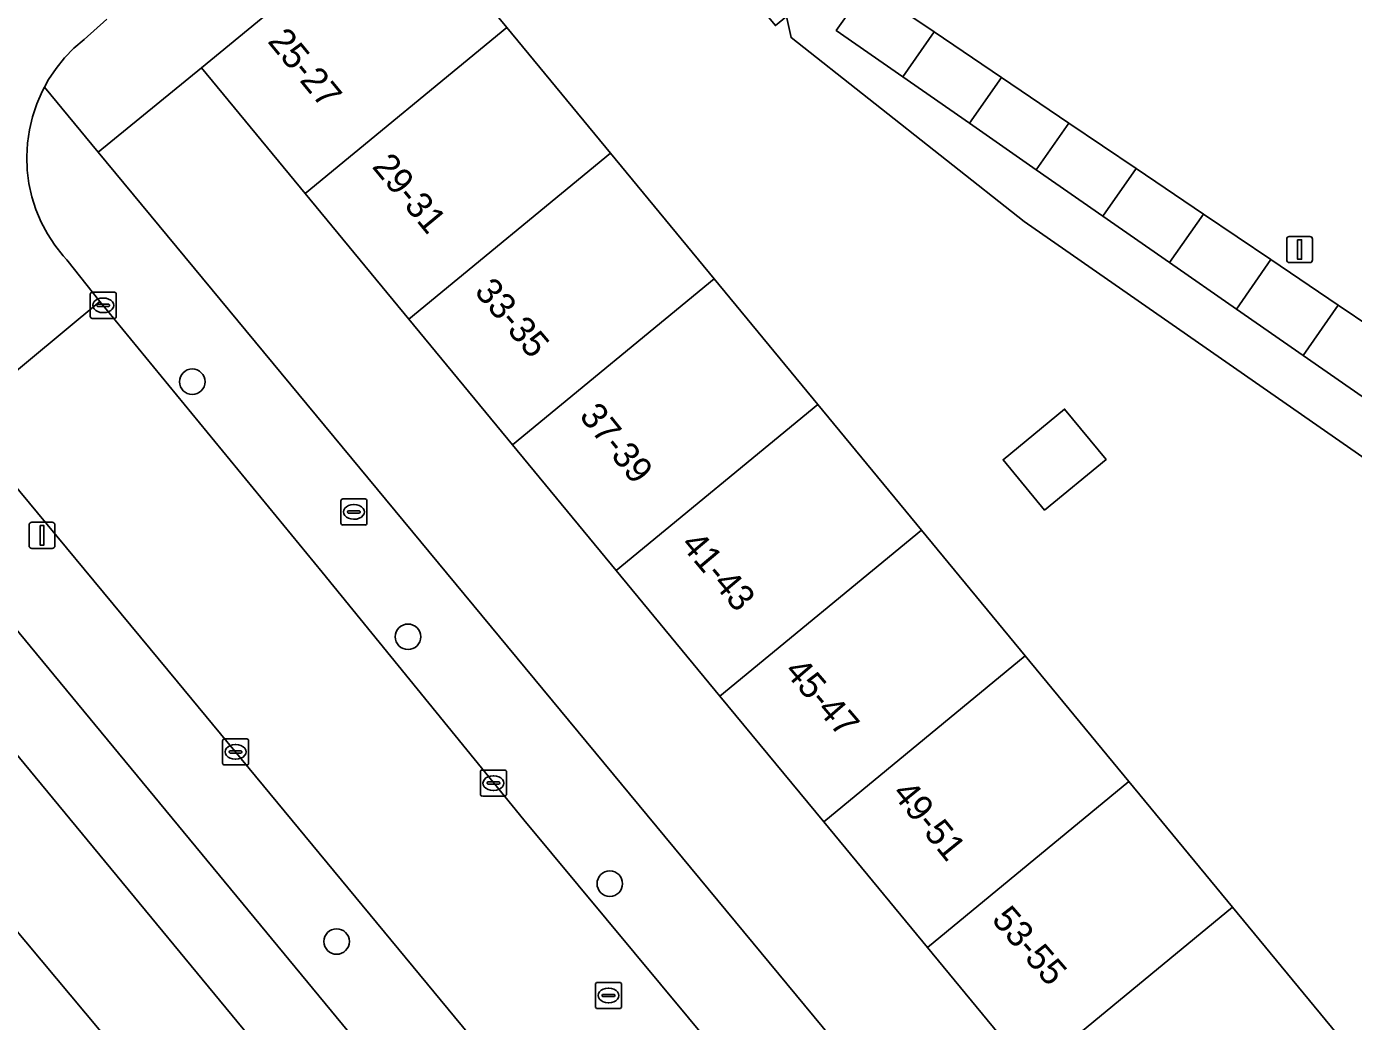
# Model space of a CAD drawing. Extents: x 159279 to 160377, y 384531 to 385888.
# Drawn here: x 159508.6 to 159559.4, y 385070.4 to 385108.5 of the extents above; entities that cross this region are included whole.
import ezdxf

# ---------------------------------------------------------------- set-up
doc = ezdxf.new("R2010")
doc.units = 0
for name, color, linetype in [('IMGEO_Berm_groen', 7, 'Continuous'), ('IMGEO_Boom', 7, 'Continuous'), ('IMGEO_Brandkraan', 7, 'Continuous'), ('IMGEO_Erf', 7, 'Continuous'), ('IMGEO_Fietspad_open', 7, 'Continuous'), ('IMGEO_Kolk', 7, 'Continuous'), ('IMGEO_Lichtmast', 7, 'Continuous'), ('IMGEO_Pand', 7, 'Continuous'), ('IMGEO_Pand_nummerreeks', 7, 'Continuous'), ('IMGEO_Rijbaan_lokaal_open', 7, 'Continuous'), ('IMGEO_Rioolput', 7, 'Continuous'), ('IMGEO_Voetpad_halfverhard', 7, 'Continuous'), ('IMGEO_Voetpad_open', 7, 'Continuous')]:
    doc.layers.add(name, color=color, linetype=linetype)

msp = doc.modelspace()

# ---------------------------------------------------------------- linework, layer by layer
at = {"layer": 'IMGEO_Berm_groen'}
msp.add_lwpolyline([(159548.464, 385042.144), (159514.365, 385083.398), (159506.522, 385092.845), (159505.985, 385093.489), (159501.236, 385099.246), (159500, 385098.236), (159498.552, 385097.053), (159500, 385095.299), (159503.322, 385091.276), (159555.379, 385028.229), (159578.758, 385000), (159595.338, 384979.98), (159599.426, 384980.154), (159597.476, 384982.555), (159597.475, 384982.557), (159592.173, 384989.226), (159583.28, 385000), (159567.948, 385018.574), (159561.44, 385026.479)], dxfattribs=at)
msp.add_lwpolyline([(159500.989, 385089.338), (159500, 385090.536), (159496.167, 385095.18), (159492.847, 385092.45), (159504.614, 385078.11), (159526.057, 385052.483), (159550.045, 385023.323), (159581.191, 384985.668), (159588.005, 384977.223), (159607.336, 384953.936), (159608.885, 384958.557), (159603.858, 384964.651), (159595.683, 384974.49), (159595.245, 384975.018), (159581.364, 384991.732), (159572.259, 385003.065), (159553.043, 385026.266)], close=True, dxfattribs=at)
at = {"layer": 'IMGEO_Boom'}
for centre in [(159514.928, 385094.896), (159523.196, 385085.12), (159530.928, 385075.656), (159520.459, 385073.439)]:
    msp.add_circle(centre, 0.489, dxfattribs=at)
at = {"layer": 'IMGEO_Brandkraan'}
for p, q in [((159520.621, 385089.478), (159520.621, 385090.33)), ((159520.696, 385090.404), (159521.548, 385090.404)), ((159521.622, 385090.33), (159521.622, 385089.478)), ((159520.88, 385089.898), (159520.88, 385089.91)), ((159521.318, 385089.861), (159520.92, 385089.861)), ((159520.923, 385089.947), (159521.321, 385089.947)), ((159521.109, 385090.184), (159521.134, 385090.184)), ((159521.364, 385089.91), (159521.364, 385089.898)), ((159521.548, 385089.404), (159520.696, 385089.404)), ((159521.132, 385089.624), (159521.107, 385089.624))]:
    msp.add_line(p, q, dxfattribs=at)
for points in [[(159520.621, 385089.478), (159520.621, 385090.33)], [(159520.696, 385090.404), (159521.548, 385090.404)], [(159521.622, 385090.33), (159521.622, 385089.478)], [(159521.548, 385089.404), (159520.696, 385089.404)]]:
    msp.add_lwpolyline(points, dxfattribs=at)
for centre, radius, start, end in [((159520.698, 385090.328), 0.0765, 91.552, 178.448), ((159520.698, 385090.328), 0.0765, 91.552, 178.448), ((159521.546, 385090.328), 0.0765, 1.552, 88.448), ((159521.546, 385090.328), 0.0765, 1.552, 88.448), ((159520.92, 385089.907), 0.0403, 85.8775, 175.7526), ((159520.917, 385089.897), 0.0366, 178.938, 274.7102), ((159521.321, 385089.904), 0.043, 264.8664, 352.4533), ((159521.325, 385089.909), 0.0386, 1.7309, 96.639), ((159520.698, 385089.48), 0.0765, 181.552, 268.448), ((159520.698, 385089.48), 0.0765, 181.552, 268.448), ((159521.546, 385089.48), 0.0765, 271.552, 358.448), ((159521.546, 385089.48), 0.0765, 271.552, 358.448)]:
    msp.add_arc(centre, radius, start, end, dxfattribs=at)
for centre, major_axis, ratio, start_param, end_param in [((159521.108, 385089.904), (-0.387, 0.002), 0.722429, 4.712389, 7.853982), ((159521.133, 385089.904), (-0.39, 0.002), 0.717154, 1.570796, 4.712389)]:
    msp.add_ellipse(centre, major_axis=major_axis, ratio=ratio, start_param=start_param, end_param=end_param, dxfattribs=at)
at = {"layer": 'IMGEO_Erf'}
msp.add_lwpolyline([(159560.206, 385120.511), (159555.815, 385123.374), (159553.961, 385124.582), (159548.542, 385120.063), (159546.841, 385118.672), (159546.787, 385118.736), (159543.539, 385115.984), (159540.221, 385119.961), (159536.5, 385124.478), (159534.056, 385122.447), (159532.547, 385121.206), (159532.576, 385121.17), (159541.494, 385110.217), (159541.312, 385109.686), (159543.361, 385108.3), (159545.941, 385106.555), (159548.52, 385104.81), (159551.1, 385103.065), (159553.68, 385101.321), (159556.259, 385099.576), (159558.839, 385097.831), (159561.419, 385096.086)], dxfattribs=at)
for points in [[(159546.804, 385101.034), (159537.877, 385108.087), (159537.695, 385108.891), (159537.274, 385108.543), (159533.299, 385113.344), (159535.261, 385114.967), (159533.216, 385117.531), (159531.308, 385116.022), (159529.284, 385118.582), (159523.004, 385113.291), (159526.979, 385108.475), (159530.953, 385103.659), (159534.926, 385098.843), (159538.9, 385094.026), (159542.874, 385089.21), (159546.848, 385084.394), (159550.822, 385079.578), (159554.796, 385074.761), (159558.769, 385069.945), (159562.743, 385065.129), (159566.717, 385060.312), (159570.691, 385055.496), (159580.752, 385063.798), (159587.133, 385072.965)], [(159543.1, 385073.206), (159539.126, 385078.022), (159535.152, 385082.839), (159531.178, 385087.655), (159527.204, 385092.471), (159523.231, 385097.288), (159519.257, 385102.104), (159515.283, 385106.92), (159511.318, 385103.692), (159559.124, 385045.952), (159562.969, 385049.125), (159558.995, 385053.941), (159555.021, 385058.757), (159551.048, 385063.574), (159547.074, 385068.39)], [(159547.594, 385089.973), (159546, 385091.905), (159548.356, 385093.849), (159549.95, 385091.917)]]:
    msp.add_lwpolyline(points, close=True, dxfattribs=at)
at = {"layer": 'IMGEO_Fietspad_open'}
msp.add_lwpolyline([(159503.322, 385091.276), (159500, 385095.299), (159498.552, 385097.053), (159496.167, 385095.18), (159500, 385090.536), (159500.989, 385089.338), (159553.043, 385026.266), (159572.259, 385003.065), (159581.364, 384991.732), (159595.245, 384975.018), (159597.738, 384977.083), (159601.819, 384977.205), (159599.426, 384980.154), (159595.338, 384979.98), (159578.758, 385000), (159555.379, 385028.229)], close=True, dxfattribs=at)
at = {"layer": 'IMGEO_Kolk'}
for p, q in [((159511.015, 385097.397), (159511.015, 385098.249)), ((159511.09, 385098.323), (159511.942, 385098.323)), ((159511.503, 385098.103), (159511.528, 385098.103)), ((159512.016, 385098.249), (159512.016, 385097.397)), ((159511.274, 385097.817), (159511.274, 385097.829)), ((159511.712, 385097.78), (159511.314, 385097.78)), ((159511.317, 385097.866), (159511.715, 385097.866)), ((159511.526, 385097.543), (159511.501, 385097.543)), ((159511.758, 385097.829), (159511.758, 385097.817)), ((159511.942, 385097.323), (159511.09, 385097.323)), ((159516.161, 385081.207), (159517.013, 385081.207)), ((159516.086, 385080.281), (159516.086, 385081.133)), ((159516.345, 385080.701), (159516.345, 385080.713)), ((159516.783, 385080.664), (159516.385, 385080.664)), ((159516.388, 385080.75), (159516.786, 385080.75)), ((159516.574, 385080.987), (159516.599, 385080.987)), ((159516.829, 385080.713), (159516.829, 385080.701)), ((159517.087, 385081.133), (159517.087, 385080.281)), ((159517.013, 385080.207), (159516.161, 385080.207)), ((159516.597, 385080.427), (159516.572, 385080.427)), ((159525.969, 385079.086), (159525.969, 385079.938)), ((159526.044, 385080.012), (159526.896, 385080.012)), ((159526.457, 385079.792), (159526.482, 385079.792)), ((159526.97, 385079.938), (159526.97, 385079.086)), ((159526.228, 385079.506), (159526.228, 385079.518)), ((159526.666, 385079.469), (159526.268, 385079.469)), ((159526.271, 385079.555), (159526.669, 385079.555)), ((159526.48, 385079.232), (159526.455, 385079.232)), ((159526.712, 385079.518), (159526.712, 385079.506)), ((159526.896, 385079.012), (159526.044, 385079.012))]:
    msp.add_line(p, q, dxfattribs=at)
for points in [[(159511.015, 385097.397), (159511.015, 385098.249)], [(159511.09, 385098.323), (159511.942, 385098.323)], [(159512.016, 385098.249), (159512.016, 385097.397)], [(159511.942, 385097.323), (159511.09, 385097.323)], [(159516.161, 385081.207), (159517.013, 385081.207)], [(159516.086, 385080.281), (159516.086, 385081.133)], [(159517.087, 385081.133), (159517.087, 385080.281)], [(159517.013, 385080.207), (159516.161, 385080.207)], [(159525.969, 385079.086), (159525.969, 385079.938)], [(159526.044, 385080.012), (159526.896, 385080.012)], [(159526.97, 385079.938), (159526.97, 385079.086)], [(159526.896, 385079.012), (159526.044, 385079.012)]]:
    msp.add_lwpolyline(points, dxfattribs=at)
for centre, radius, start, end in [((159511.092, 385098.247), 0.0765, 91.552, 178.448), ((159511.092, 385098.247), 0.0765, 91.552, 178.448), ((159511.94, 385098.247), 0.0765, 1.552, 88.448), ((159511.94, 385098.247), 0.0765, 1.552, 88.448), ((159511.314, 385097.826), 0.0403, 85.8775, 175.7526), ((159511.311, 385097.816), 0.0366, 178.938, 274.7102), ((159511.715, 385097.823), 0.043, 264.8664, 352.4533), ((159511.719, 385097.828), 0.0386, 1.7309, 96.639), ((159511.092, 385097.399), 0.0765, 181.552, 268.448), ((159511.092, 385097.399), 0.0765, 181.552, 268.448), ((159511.94, 385097.399), 0.0765, 271.552, 358.448), ((159511.94, 385097.399), 0.0765, 271.552, 358.448), ((159516.163, 385081.131), 0.0765, 91.552, 178.448), ((159516.163, 385081.131), 0.0765, 91.552, 178.448), ((159517.011, 385081.131), 0.0765, 1.552, 88.448), ((159517.011, 385081.131), 0.0765, 1.552, 88.448), ((159516.385, 385080.71), 0.0403, 85.8775, 175.7526), ((159516.382, 385080.7), 0.0366, 178.938, 274.7102), ((159516.786, 385080.707), 0.043, 264.8664, 352.4533), ((159516.79, 385080.712), 0.0386, 1.7309, 96.639), ((159516.163, 385080.283), 0.0765, 181.552, 268.448), ((159516.163, 385080.283), 0.0765, 181.552, 268.448), ((159517.011, 385080.283), 0.0765, 271.552, 358.448), ((159517.011, 385080.283), 0.0765, 271.552, 358.448), ((159526.046, 385079.936), 0.0765, 91.552, 178.448), ((159526.046, 385079.936), 0.0765, 91.552, 178.448), ((159526.894, 385079.936), 0.0765, 1.552, 88.448), ((159526.894, 385079.936), 0.0765, 1.552, 88.448), ((159526.268, 385079.515), 0.0403, 85.8775, 175.7526), ((159526.265, 385079.505), 0.0366, 178.938, 274.7102), ((159526.669, 385079.512), 0.043, 264.8664, 352.4533), ((159526.673, 385079.517), 0.0386, 1.7309, 96.639), ((159526.046, 385079.088), 0.0765, 181.552, 268.448), ((159526.046, 385079.088), 0.0765, 181.552, 268.448), ((159526.894, 385079.088), 0.0765, 271.552, 358.448), ((159526.894, 385079.088), 0.0765, 271.552, 358.448)]:
    msp.add_arc(centre, radius, start, end, dxfattribs=at)
for centre, major_axis, ratio, start_param, end_param in [((159511.502, 385097.823), (-0.387, 0.002), 0.722429, 4.712389, 7.853982), ((159511.527, 385097.823), (-0.39, 0.002), 0.717154, 1.570796, 4.712389), ((159516.573, 385080.707), (-0.387, 0.002), 0.722429, 4.712389, 7.853982), ((159516.598, 385080.707), (-0.39, 0.002), 0.717154, 1.570796, 4.712389), ((159526.456, 385079.512), (-0.387, 0.002), 0.722429, 4.712389, 7.853982), ((159526.481, 385079.512), (-0.39, 0.002), 0.717154, 1.570796, 4.712389)]:
    msp.add_ellipse(centre, major_axis=major_axis, ratio=ratio, start_param=start_param, end_param=end_param, dxfattribs=at)
at = {"layer": 'IMGEO_Lichtmast'}
for p, q in [((159556.87, 385099.562), (159556.87, 385100.362)), ((159556.87, 385100.362), (159556.87, 385099.562)), ((159556.97, 385100.462), (159557.76, 385100.462)), ((159557.76, 385100.462), (159556.97, 385100.462)), ((159557.86, 385100.362), (159557.86, 385099.562)), ((159557.86, 385099.562), (159557.86, 385100.362)), ((159557.76, 385099.462), (159556.97, 385099.462)), ((159556.97, 385099.462), (159557.76, 385099.462)), ((159508.674, 385088.609), (159508.674, 385089.409)), ((159508.674, 385089.409), (159508.674, 385088.609)), ((159508.774, 385089.509), (159509.564, 385089.509)), ((159509.564, 385089.509), (159508.774, 385089.509)), ((159509.664, 385089.409), (159509.664, 385088.609)), ((159509.664, 385088.609), (159509.664, 385089.409)), ((159509.564, 385088.509), (159508.774, 385088.509)), ((159508.774, 385088.509), (159509.564, 385088.509))]:
    msp.add_line(p, q, dxfattribs=at)
for points in [[(159557.29, 385100.337), (159557.44, 385100.337), (159557.44, 385099.587), (159557.29, 385099.587), (159557.29, 385100.337)], [(159509.094, 385089.384), (159509.244, 385089.384), (159509.244, 385088.634), (159509.094, 385088.634), (159509.094, 385089.384)]]:
    msp.add_lwpolyline(points, dxfattribs=at)
for centre, start, end in [((159556.97, 385100.362), 90, 180), ((159556.97, 385100.362), 90, 180), ((159557.76, 385100.362), 0, 90), ((159557.76, 385100.362), 360, 90), ((159556.97, 385099.562), 180, 270), ((159556.97, 385099.562), 180, 270), ((159557.76, 385099.562), 270, 0), ((159557.76, 385099.562), 270, 0), ((159508.774, 385089.409), 90, 180), ((159508.774, 385089.409), 90, 180), ((159509.564, 385089.409), 0, 90), ((159509.564, 385089.409), 360, 90), ((159508.774, 385088.609), 180, 270), ((159508.774, 385088.609), 180, 270), ((159509.564, 385088.609), 270, 0), ((159509.564, 385088.609), 270, 0)]:
    msp.add_arc(centre, 0.1, start, end, dxfattribs=at)
at = {"layer": 'IMGEO_Pand'}
for points in [[(159519.257, 385102.104), (159526.979, 385108.475), (159523.004, 385113.291), (159515.283, 385106.92)], [(159541.312, 385109.686), (159540.781, 385110.045), (159540.454, 385109.575), (159539.607, 385108.358), (159542.162, 385106.579), (159543.361, 385108.3)], [(159523.231, 385097.288), (159530.953, 385103.659), (159526.979, 385108.475), (159519.257, 385102.104)], [(159545.941, 385106.555), (159543.361, 385108.3), (159542.162, 385106.579), (159544.718, 385104.799)], [(159548.52, 385104.81), (159545.941, 385106.555), (159544.718, 385104.799), (159547.273, 385103.02)], [(159551.1, 385103.065), (159548.52, 385104.81), (159547.273, 385103.02), (159549.829, 385101.24)], [(159527.204, 385092.471), (159534.926, 385098.843), (159530.953, 385103.659), (159523.231, 385097.288)], [(159553.68, 385101.321), (159551.1, 385103.065), (159549.829, 385101.24), (159552.384, 385099.461)], [(159552.384, 385099.461), (159554.94, 385097.681), (159556.259, 385099.576), (159553.68, 385101.321)], [(159558.839, 385097.831), (159556.259, 385099.576), (159554.94, 385097.681), (159557.495, 385095.901)], [(159531.178, 385087.655), (159538.9, 385094.026), (159534.926, 385098.843), (159527.204, 385092.471)], [(159557.495, 385095.901), (159560.051, 385094.122), (159561.419, 385096.086), (159558.839, 385097.831)], [(159535.152, 385082.839), (159542.874, 385089.21), (159538.9, 385094.026), (159531.178, 385087.655)], [(159546, 385091.905), (159547.594, 385089.973), (159549.95, 385091.917), (159548.356, 385093.849)], [(159539.126, 385078.022), (159546.848, 385084.394), (159542.874, 385089.21), (159535.152, 385082.839)], [(159543.1, 385073.206), (159550.822, 385079.578), (159546.848, 385084.394), (159539.126, 385078.022)], [(159547.074, 385068.39), (159554.796, 385074.761), (159550.822, 385079.578), (159543.1, 385073.206)], [(159551.048, 385063.574), (159558.769, 385069.945), (159554.796, 385074.761), (159547.074, 385068.39)]]:
    msp.add_lwpolyline(points, close=True, dxfattribs=at)
at = {"layer": 'IMGEO_Rijbaan_lokaal_open'}
for points in [[(159505.985, 385093.489), (159511.383, 385097.972), (159510.116, 385099.561), (159509.978, 385099.717), (159509.659, 385100.124), (159509.378, 385100.558), (159509.137, 385101.016), (159508.937, 385101.493), (159508.782, 385101.987), (159508.67, 385102.492), (159508.605, 385103.005), (159508.585, 385103.522), (159508.612, 385104.038), (159508.685, 385104.551), (159508.803, 385105.054), (159508.966, 385105.545), (159509.172, 385106.02), (159509.259, 385106.179), (159509.419, 385106.474), (159509.707, 385106.904), (159510.031, 385107.307), (159510.39, 385107.679), (159510.781, 385108.018), (159511.649, 385108.789)], [(159557.185, 385042.623), (159553.833, 385046.695), (159544.482, 385057.841), (159527.632, 385078.097), (159519.905, 385087.599), (159511.383, 385097.972), (159505.985, 385093.489), (159506.522, 385092.845), (159514.365, 385083.398), (159548.464, 385042.144), (159554.532, 385034.81)]]:
    msp.add_lwpolyline(points, dxfattribs=at)
at = {"layer": 'IMGEO_Rioolput'}
for p, q in [((159530.379, 385070.944), (159530.379, 385071.796)), ((159530.454, 385071.87), (159531.306, 385071.87)), ((159530.867, 385071.65), (159530.892, 385071.65)), ((159531.38, 385071.796), (159531.38, 385070.944)), ((159530.638, 385071.364), (159530.638, 385071.376)), ((159531.076, 385071.327), (159530.678, 385071.327)), ((159530.681, 385071.413), (159531.079, 385071.413)), ((159530.89, 385071.09), (159530.865, 385071.09)), ((159531.122, 385071.376), (159531.122, 385071.364)), ((159531.306, 385070.87), (159530.454, 385070.87))]:
    msp.add_line(p, q, dxfattribs=at)
for points in [[(159530.379, 385070.944), (159530.379, 385071.796)], [(159530.454, 385071.87), (159531.306, 385071.87)], [(159531.38, 385071.796), (159531.38, 385070.944)], [(159531.306, 385070.87), (159530.454, 385070.87)]]:
    msp.add_lwpolyline(points, dxfattribs=at)
for centre, radius, start, end in [((159530.456, 385071.794), 0.0765, 91.552, 178.448), ((159530.456, 385071.794), 0.0765, 91.552, 178.448), ((159531.304, 385071.794), 0.0765, 1.552, 88.448), ((159531.304, 385071.794), 0.0765, 1.552, 88.448), ((159530.678, 385071.373), 0.0403, 85.8775, 175.7526), ((159530.675, 385071.363), 0.0366, 178.938, 274.7102), ((159531.079, 385071.37), 0.043, 264.8664, 352.4533), ((159531.083, 385071.375), 0.0386, 1.7309, 96.639), ((159530.456, 385070.946), 0.0765, 181.552, 268.448), ((159530.456, 385070.946), 0.0765, 181.552, 268.448), ((159531.304, 385070.946), 0.0765, 271.552, 358.448), ((159531.304, 385070.946), 0.0765, 271.552, 358.448)]:
    msp.add_arc(centre, radius, start, end, dxfattribs=at)
for centre, major_axis, ratio, start_param, end_param in [((159530.866, 385071.37), (-0.387, 0.002), 0.722429, 4.712389, 7.853982), ((159530.891, 385071.37), (-0.39, 0.002), 0.717154, 1.570796, 4.712389)]:
    msp.add_ellipse(centre, major_axis=major_axis, ratio=ratio, start_param=start_param, end_param=end_param, dxfattribs=at)
at = {"layer": 'IMGEO_Voetpad_halfverhard'}
msp.add_lwpolyline([(159492.847, 385092.45), (159490.493, 385090.52), (159501.009, 385077.693), (159516.518, 385059.136), (159548.14, 385020.507), (159580.094, 384981.698), (159581.213, 384980.339), (159607.67, 384948.458), (159609.789, 384950.769), (159611.069, 384955.91), (159609.221, 384958.15), (159608.885, 384958.557), (159607.336, 384953.936), (159588.005, 384977.223), (159581.191, 384985.668), (159550.045, 385023.323), (159526.057, 385052.483), (159504.614, 385078.11)], close=True, dxfattribs=at)
at = {"layer": 'IMGEO_Voetpad_open'}
for points in [[(159511.649, 385108.789), (159510.781, 385108.018), (159510.39, 385107.679), (159510.031, 385107.307), (159509.707, 385106.904), (159509.419, 385106.474), (159509.259, 385106.179), (159511.318, 385103.692), (159515.283, 385106.92), (159523.004, 385113.291)], [(159560.051, 385094.122), (159557.495, 385095.901), (159554.94, 385097.681), (159552.384, 385099.461), (159549.829, 385101.24), (159547.273, 385103.02), (159544.718, 385104.799), (159542.162, 385106.579), (159539.607, 385108.358), (159540.454, 385109.575), (159539.339, 385110.253), (159537.695, 385108.891), (159537.877, 385108.087), (159546.804, 385101.034), (159587.133, 385072.965)], [(159559.124, 385045.952), (159511.318, 385103.692), (159509.259, 385106.179), (159509.172, 385106.02), (159508.966, 385105.545), (159508.803, 385105.054), (159508.685, 385104.551), (159508.612, 385104.038), (159508.585, 385103.522), (159508.605, 385103.005), (159508.67, 385102.492), (159508.782, 385101.987), (159508.937, 385101.493), (159509.137, 385101.016), (159509.378, 385100.558), (159509.659, 385100.124), (159509.978, 385099.717), (159510.116, 385099.561), (159511.383, 385097.972), (159519.905, 385087.599), (159527.632, 385078.097), (159544.482, 385057.841)]]:
    msp.add_lwpolyline(points, dxfattribs=at)

# ---------------------------------------------------------------- texts
at = {"layer": 'IMGEO_Pand_nummerreeks'}
for s, rotation, p in [('25-27', 309.4709, (159517.785, 385107.93)), ('29-31', 309.5396, (159521.788, 385103.127)), ('33-35', 310.5423, (159525.708, 385098.33)), ('37-39', 308.8979, (159529.729, 385093.57)), ('41-43', 310.061, (159533.611, 385088.634)), ('45-47', 310.6569, (159537.582, 385083.777)), ('49-51', 309.0698, (159541.714, 385079.103)), ('53-55', 310.8861, (159545.529, 385074.257))]:
    msp.add_text(s, height=1, rotation=rotation, dxfattribs=at).set_placement(p)

doc.saveas('drawing.dxf')
